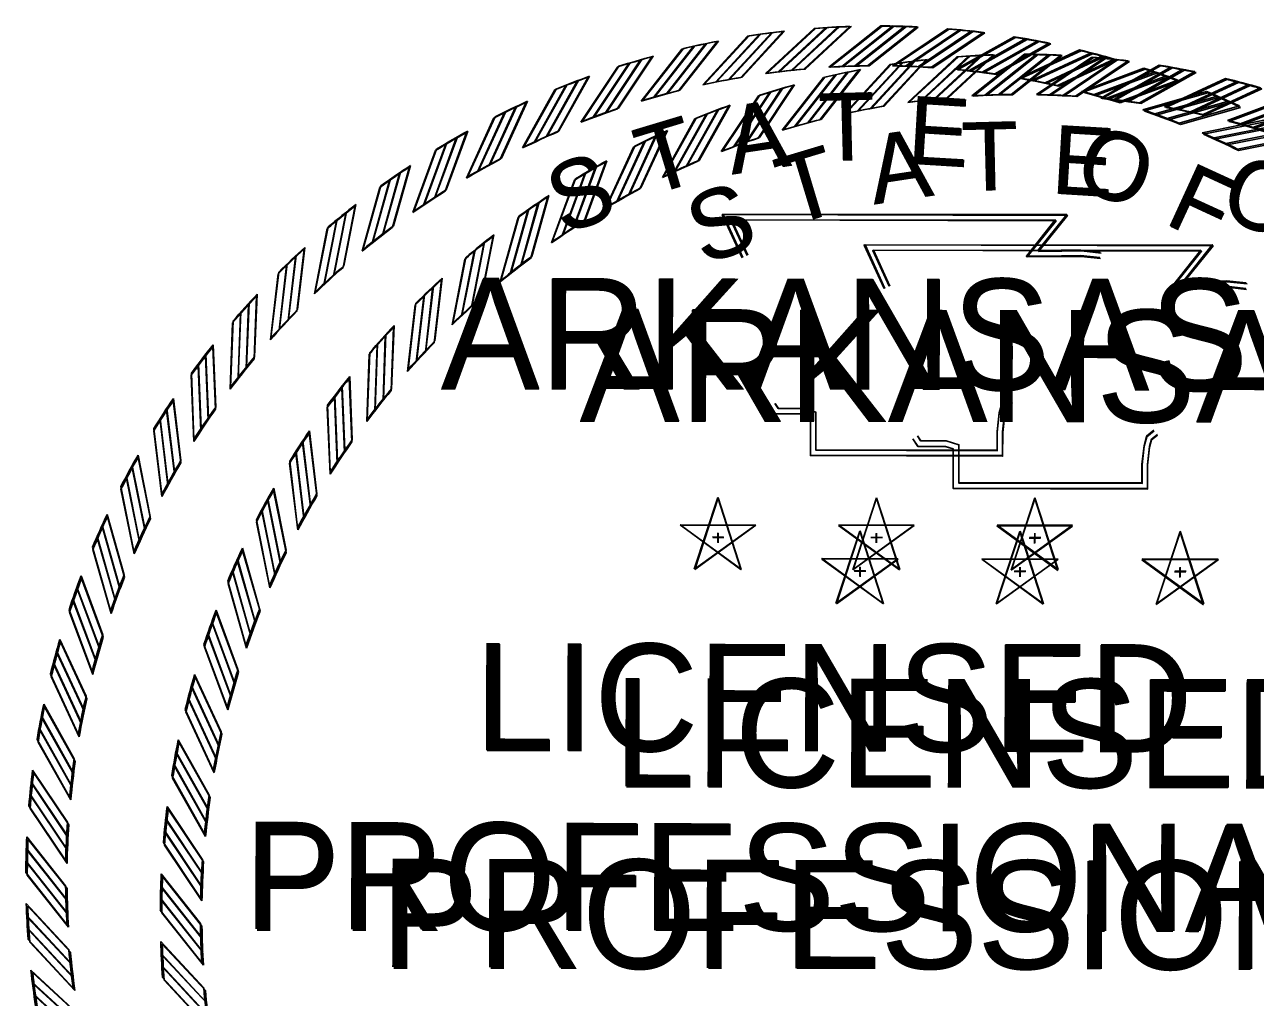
# Model space of a CAD drawing. Extents: x 1373884 to 1377798, y 1168424 to 1170626.
# Drawn here: x 1376715.2 to 1376888.6, y 1168541.9 to 1168679 of the extents above; entities that cross this region are included whole.
import ezdxf

# ---------------------------------------------------------------- set-up
doc = ezdxf.new("R2010")
doc.units = 0
for name, color, linetype in [('Default', 7, 'Continuous'), ('G-ANNO-SYMB', 7, 'Continuous'), ('G-ANNO-TEXT', 7, 'Continuous')]:
    doc.layers.add(name, color=color, linetype=linetype)

# ---------------------------------------------------------------- blocks, each defined once
blk = doc.blocks.new('STAR')
at = {"layer": 'Default'}
for p, q in [((-0.0001, 0.0615), (-0.0366, -0.0504)), ((0.0362, -0.0503), (0, 0.0617)), ((0.0587, 0.0188), (-0.059, 0.0189)), ((-0.0589, 0.0188), (0.0363, -0.0505)), ((-0.0365, -0.0503), (0.0589, 0.0188)), ((-0.0085, 0), (0.009, 0)), ((0, 0.0063), (0, -0.0085))]:
    blk.add_line(p, q, dxfattribs=at)
blk = doc.blocks.new('RP')
at = {"layer": 'Default'}
for p, q in [((-0.0781, 1.2656), (0.003, 1.33)), ((-0.058, 1.2667), (0.0216, 1.3299)), ((-0.0375, 1.2674), (0.0405, 1.3294)), ((-0.0176, 1.2679), (0.059, 1.3287))]:
    blk.add_line(p, q, dxfattribs=at)
for radius, start, end in [(1.33, 87.4562, 89.8699), (1.268, 90.7933, 93.5307)]:
    blk.add_arc((0, 0), radius, start, end, dxfattribs=at)

msp = doc.modelspace()

# ---------------------------------------------------------------- linework, layer by layer
at = {"layer": 'Default'}
for points in [[(1376836.31, 1168641.78), (1376833.48, 1168647.92), (1376882.52, 1168647.95), (1376878.42, 1168642.8), (1376881.75, 1168642.84), (1376884.54, 1168642.88), (1376887.32, 1168642.58)], [(1376836.41, 1168641.81), (1376833.6, 1168647.96), (1376882.64, 1168647.82), (1376878.52, 1168642.69), (1376881.85, 1168642.72), (1376884.64, 1168642.75), (1376887.42, 1168642.44)], [(1376837.02, 1168642.11), (1376834.69, 1168647.14), (1376880.91, 1168647.17), (1376876.8, 1168642), (1376881.76, 1168642.07), (1376884.5, 1168642.1), (1376887.23, 1168641.8)], [(1376837.12, 1168642.14), (1376834.81, 1168647.18), (1376881.02, 1168647.05), (1376876.89, 1168641.9), (1376881.86, 1168641.94), (1376884.6, 1168641.97), (1376887.33, 1168641.66)], [(1376874.79, 1168621.23), (1376873.96, 1168620.55), (1376873.68, 1168619.53), (1376873.4, 1168616.99), (1376873.4, 1168613.6), (1376846.03, 1168613.6), (1376846.03, 1168618.18), (1376846.03, 1168619.19), (1376844.91, 1168619.53), (1376841.02, 1168619.53), (1376840.33, 1168620.59)], [(1376874.82, 1168621.13), (1376873.98, 1168620.45), (1376873.7, 1168619.44), (1376873.41, 1168616.9), (1376873.4, 1168613.51), (1376846.03, 1168613.6), (1376846.04, 1168618.18), (1376846.04, 1168619.19), (1376844.94, 1168619.54), (1376841.04, 1168619.55), (1376840.35, 1168620.61)], [(1376874.3, 1168621.83), (1376873.27, 1168620.99), (1376872.91, 1168619.68), (1376872.62, 1168617.03), (1376872.62, 1168614.38), (1376846.8, 1168614.38), (1376846.8, 1168618.18), (1376846.8, 1168619.77), (1376845.03, 1168620.31), (1376841.44, 1168620.31), (1376840.98, 1168621.01)], [(1376874.33, 1168621.74), (1376873.3, 1168620.9), (1376872.93, 1168619.59), (1376872.64, 1168616.94), (1376872.63, 1168614.29), (1376846.8, 1168614.37), (1376846.82, 1168618.17), (1376846.82, 1168619.77), (1376845.05, 1168620.31), (1376841.46, 1168620.33), (1376841, 1168621.03)]]:
    msp.add_lwpolyline(points, dxfattribs=at)
at = {"layer": 'G-ANNO-SYMB'}
for points in [[(1376816.29, 1168646.13), (1376813.49, 1168652.2), (1376862.01, 1168652.23), (1376857.95, 1168647.13), (1376861.25, 1168647.18), (1376864, 1168647.21), (1376866.75, 1168646.91)], [(1376816.39, 1168646.16), (1376813.6, 1168652.24), (1376862.12, 1168652.1), (1376858.05, 1168647.02), (1376861.35, 1168647.06), (1376864.1, 1168647.08), (1376866.85, 1168646.77)], [(1376816.99, 1168646.45), (1376814.69, 1168651.43), (1376860.41, 1168651.46), (1376856.34, 1168646.34), (1376861.26, 1168646.41), (1376863.97, 1168646.44), (1376866.67, 1168646.15)], [(1376817.09, 1168646.48), (1376814.8, 1168651.47), (1376860.53, 1168651.34), (1376856.44, 1168646.24), (1376861.35, 1168646.29), (1376864.06, 1168646.31), (1376866.77, 1168646.01)], [(1376853.88, 1168626.39), (1376852.86, 1168625.56), (1376852.5, 1168624.26), (1376852.22, 1168621.64), (1376852.22, 1168619.01), (1376826.67, 1168619.01), (1376826.67, 1168622.77), (1376826.67, 1168624.35), (1376824.92, 1168624.88), (1376821.36, 1168624.88), (1376820.91, 1168625.58)], [(1376853.9, 1168626.29), (1376852.88, 1168625.47), (1376852.52, 1168624.17), (1376852.23, 1168621.55), (1376852.22, 1168618.92), (1376826.67, 1168619.01), (1376826.68, 1168622.77), (1376826.69, 1168624.34), (1376824.94, 1168624.89), (1376821.39, 1168624.9), (1376820.93, 1168625.6)], [(1376854.36, 1168625.79), (1376853.53, 1168625.12), (1376853.26, 1168624.11), (1376852.98, 1168621.6), (1376852.98, 1168618.24), (1376825.9, 1168618.24), (1376825.9, 1168622.77), (1376825.9, 1168623.78), (1376824.8, 1168624.11), (1376820.95, 1168624.11), (1376820.26, 1168625.16)], [(1376854.39, 1168625.7), (1376853.56, 1168625.03), (1376853.28, 1168624.02), (1376853, 1168621.51), (1376852.98, 1168618.15), (1376825.9, 1168618.24), (1376825.92, 1168622.77), (1376825.92, 1168623.78), (1376824.82, 1168624.12), (1376820.97, 1168624.13), (1376820.29, 1168625.18)]]:
    msp.add_lwpolyline(points, dxfattribs=at)

# ---------------------------------------------------------------- block references
at = {"layer": 'Default'}
for name, p, xscale, yscale, rotation in [('RP', (1376855.79, 1168553.54), 91.17655343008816, 91.1765534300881, 4.500000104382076), ('RP', (1376855.59, 1168553.5), 91.17655343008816, 91.17655343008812, 4.304199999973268), ('RP', (1376855.79, 1168553.54), 91.17655343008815, 91.1765534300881, 1.0438208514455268e-07), ('RP', (1376855.59, 1168553.5), 91.17655343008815, 91.1765534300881, -0.1958000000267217), ('RP', (1376855.79, 1168553.54), 91.17655343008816, 91.17655343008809, -4.499999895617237), ('RP', (1376855.59, 1168553.5), 91.17655343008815, 91.17655343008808, -4.695800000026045), ('RP', (1376855.79, 1168553.54), 91.17655343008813, 91.17655343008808, 9.000000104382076), ('RP', (1376855.59, 1168553.5), 91.17655343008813, 91.17655343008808, 8.804199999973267), ('RP', (1376855.79, 1168553.54), 91.17655343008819, 91.17655343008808, -8.999999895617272), ('RP', (1376855.59, 1168553.5), 91.17655343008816, 91.17655343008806, -9.19580000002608), ('RP', (1376855.79, 1168553.54), 91.17655343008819, 91.17655343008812, -13.499999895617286), ('RP', (1376855.59, 1168553.5), 91.17655343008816, 91.17655343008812, -13.695800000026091), ('RP', (1376855.79, 1168553.54), 91.17655343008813, 91.17655343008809, 13.500000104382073), ('RP', (1376855.59, 1168553.5), 91.17655343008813, 91.17655343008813, 13.304199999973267), ('RP', (1376855.79, 1168553.54), 91.17655343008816, 91.1765534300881, 18.00000010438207), ('RP', (1376855.59, 1168553.5), 91.17655343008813, 91.17655343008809, 17.80419999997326), ('RP', (1376855.79, 1168553.54), 91.17655343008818, 91.17655343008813, -17.999999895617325), ('RP', (1376855.59, 1168553.5), 91.17655343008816, 91.1765534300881, -18.195800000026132), ('RP', (1376855.59, 1168553.5), 91.17655343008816, 91.17655343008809, 22.304199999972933), ('RP', (1376855.79, 1168553.54), 91.17655343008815, 91.1765534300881, 22.500000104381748), ('RP', (1376855.79, 1168553.54), 91.17655343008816, 91.17655343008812, 27.00000010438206), ('RP', (1376855.59, 1168553.5), 91.17655343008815, 91.17655343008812, 26.80419999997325), ('RP', (1376855.79, 1168553.54), 91.1765534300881, 91.17655343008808, 31.500000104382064), ('RP', (1376855.59, 1168553.5), 91.17655343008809, 91.17655343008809, 31.30419999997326), ('RP', (1376855.79, 1168553.54), 91.17655343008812, 91.1765534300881, 36.00000010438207), ('RP', (1376855.59, 1168553.5), 91.1765534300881, 91.1765534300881, 35.804199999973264), ('RP', (1376855.79, 1168553.54), 91.17655343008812, 91.1765534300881, 40.50000010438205), ('RP', (1376855.59, 1168553.5), 91.17655343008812, 91.1765534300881, 40.30419999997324), ('RP', (1376855.79, 1168553.54), 91.17655343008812, 91.17655343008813, 45.00000010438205), ('RP', (1376855.59, 1168553.5), 91.17655343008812, 91.17655343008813, 44.80419999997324), ('RP', (1376855.59, 1168553.5), 91.17655343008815, 91.17655343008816, 49.304199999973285), ('RP', (1376855.79, 1168553.54), 91.17655343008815, 91.17655343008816, 49.500000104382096), ('RP', (1376855.79, 1168553.54), 91.17655343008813, 91.17655343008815, 54.00000010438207), ('RP', (1376855.59, 1168553.5), 91.17655343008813, 91.17655343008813, 53.804199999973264), ('RP', (1376855.59, 1168553.5), 91.1765534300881, 91.17655343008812, 58.304199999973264), ('RP', (1376855.79, 1168553.54), 91.1765534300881, 91.17655343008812, 58.50000010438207), ('RP', (1376855.59, 1168553.5), 91.17655343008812, 91.17655343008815, 62.804199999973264), ('RP', (1376855.79, 1168553.54), 91.17655343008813, 91.17655343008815, 63.000000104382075), ('STAR', (1376832.86, 1168602), 91.17655343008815, 91.1765534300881, -0.1958000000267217), ('STAR', (1376832.9, 1168601.95), 91.17655343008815, 91.1765534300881, 1.0438208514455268e-07), ('STAR', (1376855.41, 1168601.92), 91.17655343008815, 91.1765534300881, -0.1958000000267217), ('STAR', (1376855.45, 1168601.95), 91.17655343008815, 91.1765534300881, 1.0438208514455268e-07), ('STAR', (1376877.97, 1168601.84), 91.17655343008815, 91.1765534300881, -0.1958000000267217), ('STAR', (1376878.01, 1168601.95), 91.17655343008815, 91.1765534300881, 1.0438208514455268e-07), ('RP', (1376855.59, 1168553.5), 91.1765534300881, 91.17655343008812, 67.30419999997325), ('RP', (1376855.79, 1168553.54), 91.1765534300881, 91.17655343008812, 67.50000010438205), ('RP', (1376855.59, 1168553.5), 91.17655343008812, 91.17655343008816, 71.80419999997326), ('RP', (1376855.79, 1168553.54), 91.17655343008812, 91.17655343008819, 72.00000010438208), ('RP', (1376855.59, 1168553.5), 91.17655343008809, 91.17655343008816, 76.30419999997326), ('RP', (1376855.79, 1168553.54), 91.17655343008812, 91.17655343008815, 76.50000010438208), ('RP', (1376855.59, 1168553.5), 91.17655343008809, 91.17655343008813, 80.80419999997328), ('RP', (1376855.79, 1168553.54), 91.1765534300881, 91.17655343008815, 81.0000001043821), ('RP', (1376855.59, 1168553.5), 91.17655343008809, 91.17655343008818, 85.30419999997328), ('RP', (1376855.79, 1168553.54), 91.17655343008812, 91.17655343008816, 85.50000010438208), ('RP', (1376855.59, 1168553.5), 91.1765534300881, 91.17655343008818, 89.80419999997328), ('RP', (1376855.79, 1168553.54), 91.17655343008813, 91.17655343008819, 90.0000001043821), ('RP', (1376855.59, 1168553.5), 91.1765534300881, 91.17655343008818, 94.30419999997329), ('RP', (1376855.79, 1168553.54), 91.1765534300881, 91.17655343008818, 94.5000001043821)]:
    msp.add_blockref(name, p, dxfattribs=dict(at, xscale=xscale, yscale=yscale, rotation=rotation))
at = {"layer": 'G-ANNO-SYMB'}
for name, p, xscale, yscale, rotation in [('RP', (1376835.56, 1168558.82), 90.20715837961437, 90.20715837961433, 9.000000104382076), ('RP', (1376835.36, 1168558.79), 90.20715837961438, 90.20715837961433, 8.804199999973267), ('RP', (1376835.56, 1168558.82), 90.20715837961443, 90.20715837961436, 4.500000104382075), ('RP', (1376835.36, 1168558.79), 90.2071583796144, 90.20715837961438, 4.304199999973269), ('RP', (1376835.56, 1168558.82), 90.2071583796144, 90.20715837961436, 1.0438208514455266e-07), ('RP', (1376835.36, 1168558.79), 90.2071583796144, 90.20715837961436, -0.19580000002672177), ('RP', (1376835.56, 1168558.82), 90.20715837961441, 90.20715837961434, -4.499999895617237), ('RP', (1376835.36, 1168558.79), 90.20715837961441, 90.20715837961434, -4.695800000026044), ('RP', (1376835.56, 1168558.82), 90.20715837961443, 90.20715837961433, -8.999999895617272), ('RP', (1376835.36, 1168558.79), 90.20715837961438, 90.20715837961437, -9.19580000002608), ('RP', (1376835.56, 1168558.82), 90.20715837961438, 90.20715837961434, 13.500000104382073), ('RP', (1376835.36, 1168558.79), 90.2071583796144, 90.20715837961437, 13.304199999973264), ('RP', (1376835.56, 1168558.82), 90.20715837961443, 90.20715837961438, -13.499999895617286), ('RP', (1376835.36, 1168558.79), 90.20715837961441, 90.20715837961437, -13.695800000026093), ('RP', (1376835.36, 1168558.79), 90.2071583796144, 90.20715837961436, 17.804199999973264), ('RP', (1376835.56, 1168558.82), 90.20715837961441, 90.20715837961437, -17.999999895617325), ('RP', (1376835.36, 1168558.79), 90.2071583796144, 90.20715837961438, -18.19580000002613), ('RP', (1376835.56, 1168558.82), 90.20715837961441, 90.20715837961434, 18.00000010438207), ('RP', (1376835.56, 1168558.82), 90.2071583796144, 90.20715837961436, 22.500000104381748), ('RP', (1376835.36, 1168558.79), 90.2071583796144, 90.20715837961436, 22.304199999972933), ('RP', (1376835.56, 1168558.82), 90.20715837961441, 90.20715837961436, -22.499999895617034), ('RP', (1376835.36, 1168558.79), 90.20715837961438, 90.20715837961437, -22.695800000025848), ('RP', (1376835.56, 1168558.82), 90.2071583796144, 90.20715837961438, 27.000000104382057), ('RP', (1376835.36, 1168558.79), 90.2071583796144, 90.20715837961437, 26.80419999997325), ('RP', (1376835.56, 1168558.82), 90.20715837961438, 90.20715837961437, -26.999999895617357), ('RP', (1376835.36, 1168558.79), 90.2071583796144, 90.20715837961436, -27.19580000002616), ('RP', (1376835.56, 1168558.82), 90.20715837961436, 90.20715837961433, 31.50000010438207), ('RP', (1376835.36, 1168558.79), 90.20715837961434, 90.20715837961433, 31.30419999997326), ('RP', (1376835.56, 1168558.82), 90.20715837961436, 90.20715837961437, 36.00000010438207), ('RP', (1376835.36, 1168558.79), 90.20715837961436, 90.20715837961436, 35.804199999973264), ('RP', (1376835.56, 1168558.82), 90.20715837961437, 90.20715837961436, 40.50000010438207), ('RP', (1376835.36, 1168558.79), 90.20715837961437, 90.20715837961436, 40.30419999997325), ('RP', (1376835.56, 1168558.82), 90.20715837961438, 90.20715837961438, 45.00000010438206), ('RP', (1376835.36, 1168558.79), 90.20715837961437, 90.20715837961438, 44.80419999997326), ('RP', (1376835.56, 1168558.82), 90.20715837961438, 90.20715837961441, 49.500000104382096), ('RP', (1376835.36, 1168558.79), 90.20715837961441, 90.2071583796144, 49.304199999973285), ('RP', (1376835.56, 1168558.82), 90.20715837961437, 90.20715837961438, 54.00000010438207), ('RP', (1376835.36, 1168558.79), 90.20715837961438, 90.20715837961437, 53.804199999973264), ('RP', (1376835.36, 1168558.79), 90.20715837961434, 90.20715837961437, 58.304199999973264), ('RP', (1376835.56, 1168558.82), 90.20715837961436, 90.20715837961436, 58.50000010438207), ('RP', (1376835.36, 1168558.79), 90.20715837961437, 90.20715837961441, 62.804199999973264), ('RP', (1376835.56, 1168558.82), 90.20715837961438, 90.2071583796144, 63.000000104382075), ('STAR', (1376812.87, 1168606.77), 90.2071583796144, 90.20715837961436, -0.19580000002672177), ('STAR', (1376812.91, 1168606.72), 90.2071583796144, 90.20715837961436, 1.0438208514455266e-07), ('STAR', (1376835.19, 1168606.69), 90.2071583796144, 90.20715837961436, -0.19580000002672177), ('STAR', (1376835.23, 1168606.72), 90.2071583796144, 90.20715837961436, 1.0438208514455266e-07), ('STAR', (1376857.5, 1168606.61), 90.2071583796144, 90.20715837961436, -0.19580000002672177), ('STAR', (1376857.54, 1168606.72), 90.2071583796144, 90.20715837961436, 1.0438208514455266e-07), ('RP', (1376835.36, 1168558.79), 90.20715837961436, 90.2071583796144, 67.30419999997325), ('RP', (1376835.56, 1168558.82), 90.20715837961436, 90.20715837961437, 67.50000010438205), ('RP', (1376835.36, 1168558.79), 90.20715837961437, 90.2071583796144, 71.80419999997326), ('RP', (1376835.56, 1168558.82), 90.20715837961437, 90.20715837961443, 72.00000010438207), ('RP', (1376835.36, 1168558.79), 90.20715837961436, 90.2071583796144, 76.30419999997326), ('RP', (1376835.56, 1168558.82), 90.20715837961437, 90.20715837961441, 76.50000010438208), ('RP', (1376835.36, 1168558.79), 90.20715837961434, 90.20715837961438, 80.80419999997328), ('RP', (1376835.56, 1168558.82), 90.20715837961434, 90.20715837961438, 81.0000001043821), ('RP', (1376835.36, 1168558.79), 90.20715837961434, 90.20715837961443, 85.30419999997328), ('RP', (1376835.56, 1168558.82), 90.20715837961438, 90.2071583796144, 85.50000010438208), ('RP', (1376835.36, 1168558.79), 90.20715837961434, 90.20715837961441, 89.80419999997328), ('RP', (1376835.56, 1168558.82), 90.20715837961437, 90.20715837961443, 90.0000001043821), ('RP', (1376835.36, 1168558.79), 90.20715837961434, 90.20715837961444, 94.30419999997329), ('RP', (1376835.56, 1168558.82), 90.20715837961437, 90.20715837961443, 94.5000001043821), ('RP', (1376835.36, 1168558.79), 90.20715837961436, 90.20715837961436, 98.8041999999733), ('RP', (1376835.56, 1168558.82), 90.20715837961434, 90.20715837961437, 99.0000001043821)]:
    msp.add_blockref(name, p, dxfattribs=dict(at, xscale=xscale, yscale=yscale, rotation=rotation))

# ---------------------------------------------------------------- texts
at = {"layer": 'Default'}
for s, height, rotation, p in [('T', 9.67, 1.4789, (1376847.31, 1168655.51)), ('T', 9.67, 1.2831, (1376847.45, 1168655.51)), ('E', 9.67, 356.672, (1376859.69, 1168655.22)), ('E', 9.67, 356.4762, (1376859.83, 1168655.17)), ('A', 9.67, 8.6788, (1376834.82, 1168653.59)), ('A', 9.67, 8.483, (1376834.95, 1168653.63)), ('T', 9.67, 16.9015, (1376823.07, 1168650.52)), ('T', 9.67, 16.7057, (1376823.2, 1168650.6)), ('O', 9.67, 341.2218, (1376883.18, 1168651.9)), ('O', 9.67, 341.026, (1376883.31, 1168651.77)), ('S', 9.67, 19.7726, (1376810.77, 1168645)), ('S', 9.67, 19.5768, (1376810.88, 1168645.12)), ('ARKANSAS', 15.788, 0, (1376793.39, 1168622.99)), ('ARKANSAS', 15.788, 359.8042, (1376793.42, 1168623.17)), ('LICENSED', 15.285, 359.8042, (1376798.15, 1168571.62)), ('LICENSED', 15.285, 0, (1376798.29, 1168571.46)), ('PROFESSIONAL', 15.2848, 359.8042, (1376765.31, 1168546.17)), ('PROFESSIONAL', 15.2848, 0, (1376765.54, 1168545.9))]:
    msp.add_text(s, height=height, rotation=rotation, dxfattribs=at).set_placement(p)
at = {"layer": 'G-ANNO-TEXT'}
for s, height, rotation, p in [('T', 9.57, 1.4789, (1376827.17, 1168659.71)), ('T', 9.57, 1.2831, (1376827.31, 1168659.71)), ('A', 9.57, 8.6788, (1376814.81, 1168657.81)), ('A', 9.57, 8.483, (1376814.95, 1168657.84)), ('E', 9.57, 356.672, (1376839.42, 1168659.42)), ('E', 9.57, 356.4762, (1376839.56, 1168659.37)), ('T', 9.57, 16.9015, (1376803.19, 1168654.77)), ('T', 9.57, 16.7057, (1376803.32, 1168654.85)), ('O', 9.57, 341.2218, (1376862.66, 1168656.14)), ('O', 9.57, 341.026, (1376862.79, 1168656.01)), ('S', 9.57, 19.7726, (1376791.02, 1168649.31)), ('S', 9.57, 19.5768, (1376791.13, 1168649.43)), ('F', 9.57, 335.3628, (1376875.56, 1168651.09)), ('F', 9.57, 335.167, (1376875.67, 1168650.92)), ('ARKANSAS', 15.621, 0, (1376773.82, 1168627.54)), ('ARKANSAS', 15.621, 359.8042, (1376773.86, 1168627.72)), ('LICENSED', 15.122, 359.8042, (1376778.53, 1168576.71)), ('LICENSED', 15.122, 0, (1376778.67, 1168576.55)), ('PROFESSIONAL', 15.1223, 359.8042, (1376746.04, 1168551.53)), ('PROFESSIONAL', 15.1223, 0, (1376746.27, 1168551.26))]:
    msp.add_text(s, height=height, rotation=rotation, dxfattribs=at).set_placement(p)

doc.saveas('drawing.dxf')
